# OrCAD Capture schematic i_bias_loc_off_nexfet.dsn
size C
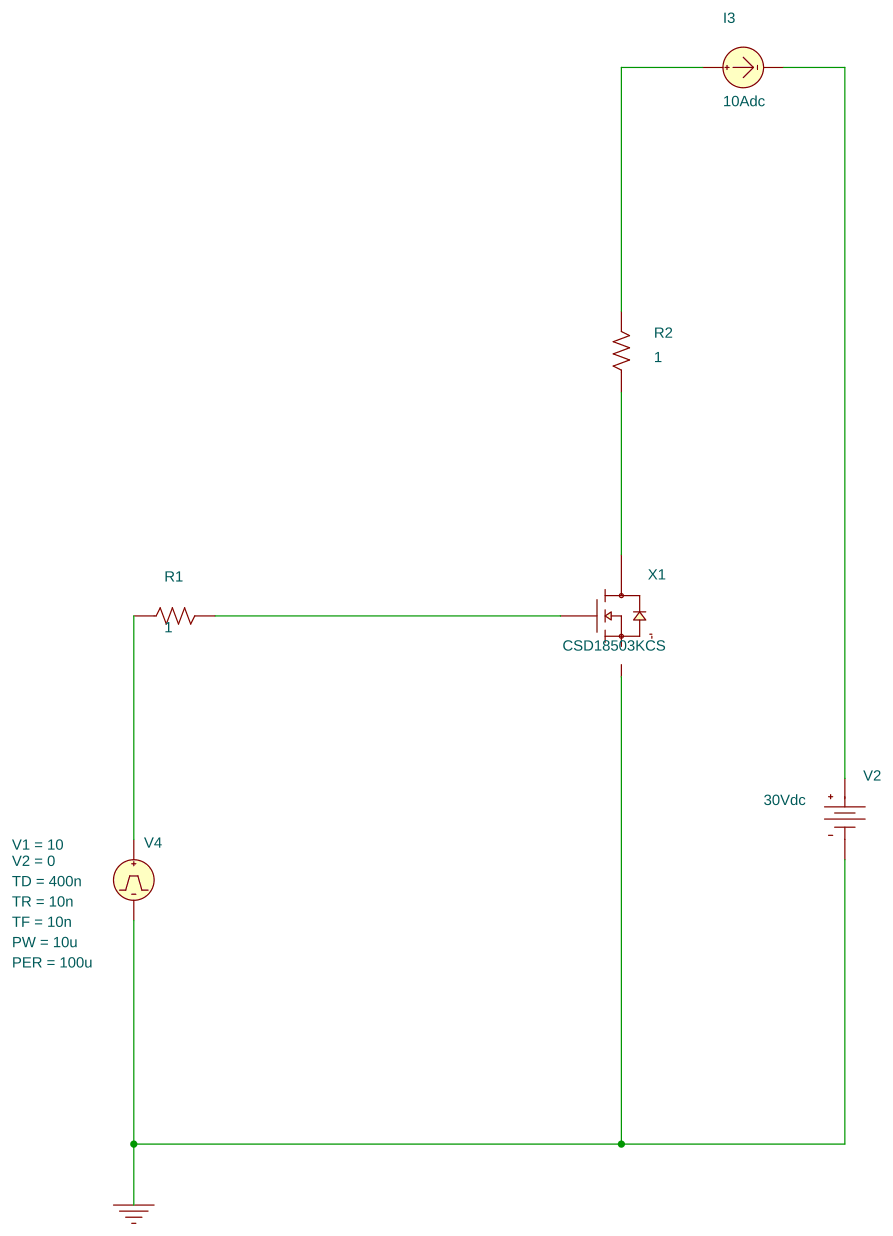
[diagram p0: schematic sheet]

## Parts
I3  IDC
R1  1  [AX/RC05]
R2  1  [AX/RC05]
V2  VDC
V4  VPULSE
X1  CSD18503KCS

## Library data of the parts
I3 = IDC: DC: 10Adc
R1 R2 = R
V2 = VDC: DC: 30Vdc
V4 = VPULSE: PER: 100u; PW: 10u; TD: 400n; TF: 10n; TR: 10n; V1: 10; V2: 0
X1 = CSD18503KCS

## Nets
0: V2.1(-) V4.2(-) X1.source
N3640832: I3.2(-) V2.0(+)
N3646128: I3.1(+) R2.2
N3669836: R1.1 V4.1(+)
N3670081: R2.1 X1.drain
N3671137: R1.2 X1.gate
